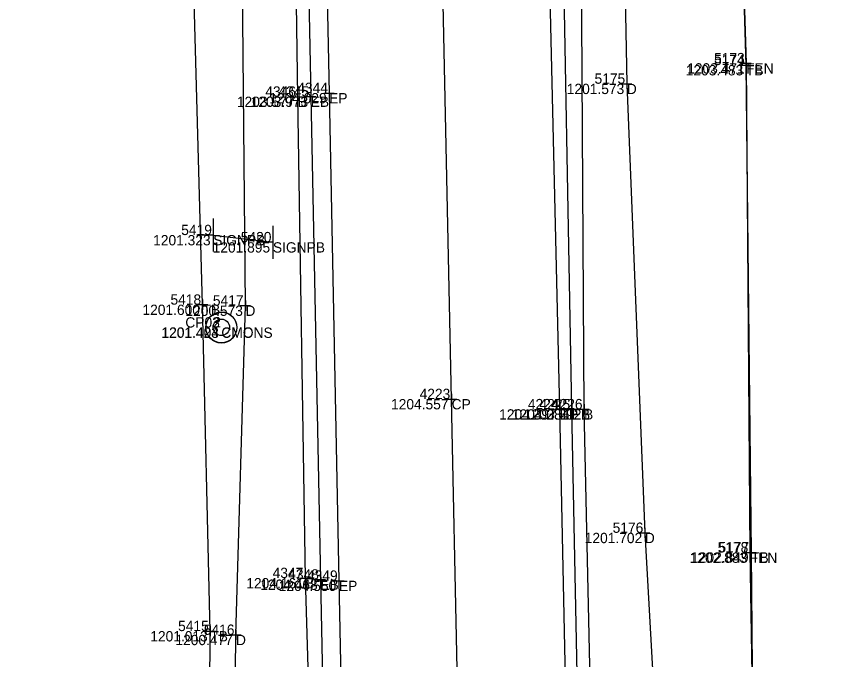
# Model space of a CAD drawing. Extents: x 2044996 to 2050343, y 455232 to 458054.
# Drawn here: x 2047583.1 to 2047663.5, y 457288.6 to 457351 of the extents above; entities that cross this region are included whole.
import ezdxf

# ---------------------------------------------------------------- set-up
doc = ezdxf.new("R2010")
doc.units = 0
for name, color, linetype in [('Default', 7, 'Continuous'), ('DR_X_Ditch', 7, 'Continuous'), ('DT_X_Contour_Minor', 7, 'Continuous'), ('DT_X_Contour_Text', 7, 'Continuous'), ('DT_X_Triangles', 7, 'Continuous'), ('DT_X_Void', 7, 'Continuous'), ('PV_X_COP', 7, 'Continuous'), ('PV_X_EOP', 7, 'Continuous'), ('PV_X_Shoulder_Aggregate', 7, 'Continuous'), ('RD_X_Fence', 7, 'Continuous'), ('SN_X_Public', 7, 'Continuous'), ('SV_P_Mon_Cells_Set', 7, 'Continuous'), ('SV_X_Break_Lines', 7, 'Continuous'), ('SV_X_Top_of_Bank', 7, 'Continuous'), ('XS_X_Ground_Line', 7, 'Continuous')]:
    doc.layers.add(name, color=color, linetype=linetype)

msp = doc.modelspace()

# ---------------------------------------------------------------- linework, layer by layer
at = {"layer": 'Default'}
msp.add_lwpolyline([(2047602.133, 457329.814), (2047607.931, 457329.117)], dxfattribs=at)
at = {"layer": 'DR_X_Ditch'}
for points in [[(2047603.882, 457240.706), (2047604.347, 457290.981), (2047605.266, 457322.964), (2047604.864, 457368.193), (2047603.186, 457417.51), (2047602.947, 457459.419), (2047602.663, 457501.838), (2047602.142, 457544.039), (2047601.082, 457584.057), (2047599.691, 457624.957), (2047599.396, 457669.272), (2047598.072, 457715.089), (2047597.975, 457762.924), (2047597.737, 457792.661), (2047596.264, 457838.201), (2047595.414, 457854.456)], [(2047635.926, 457828.454), (2047636.464, 457778.326), (2047635.665, 457731.576), (2047635.872, 457688.918), (2047636.588, 457650.583), (2047637.14, 457615.308), (2047638.364, 457574.87), (2047638.819, 457526.071), (2047639.212, 457482.918), (2047639.895, 457443.662), (2047641.237, 457398.66), (2047642.277, 457344.514), (2047644.026, 457300.889), (2047646.182, 457262.236), (2047646.962, 457237.043), (2047650.757, 457191.219), (2047650.417, 457143.89), (2047649.262, 457104.807), (2047651.899, 457052.902), (2047656.339, 457022.847)]]:
    msp.add_lwpolyline(points, dxfattribs=at)
at = {"layer": 'DT_X_Void'}
for p, q in [((2047653.853, 457347.008), (2047653.853, 457346.008)), ((2047653.326, 457346.326), (2047654.326, 457346.326)), ((2047653.353, 457346.508), (2047654.353, 457346.508)), ((2047653.826, 457346.826), (2047653.826, 457345.826)), ((2047653.826, 457346.326), (2047653.826, 457346.326)), ((2047653.853, 457346.508), (2047653.853, 457346.508)), ((2047642.277, 457345.014), (2047642.277, 457344.014)), ((2047613.384, 457344.111), (2047613.384, 457343.111)), ((2047641.777, 457344.514), (2047642.777, 457344.514)), ((2047642.277, 457344.514), (2047642.277, 457344.514)), ((2047609.815, 457343.259), (2047610.815, 457343.259)), ((2047610.315, 457343.759), (2047610.315, 457342.759)), ((2047610.315, 457343.259), (2047610.315, 457343.259)), ((2047611.099, 457343.265), (2047612.099, 457343.265)), ((2047611.599, 457343.765), (2047611.599, 457342.765)), ((2047611.599, 457343.265), (2047611.599, 457343.265)), ((2047612.884, 457343.611), (2047613.884, 457343.611)), ((2047613.384, 457343.611), (2047613.384, 457343.611)), ((2047600.608, 457323.056), (2047601.608, 457323.056)), ((2047601.108, 457323.556), (2047601.108, 457322.556)), ((2047601.108, 457323.056), (2047601.108, 457323.056)), ((2047604.766, 457322.964), (2047605.766, 457322.964)), ((2047605.266, 457323.464), (2047605.266, 457322.464)), ((2047605.266, 457322.964), (2047605.266, 457322.964)), ((2047625.275, 457314.382), (2047625.275, 457313.382)), ((2047624.775, 457313.882), (2047625.775, 457313.882)), ((2047625.275, 457313.882), (2047625.275, 457313.882)), ((2047635.764, 457313.395), (2047635.764, 457312.395)), ((2047636.928, 457313.39), (2047636.928, 457312.39)), ((2047638.128, 457313.395), (2047638.128, 457312.395)), ((2047635.264, 457312.895), (2047636.264, 457312.895)), ((2047635.764, 457312.895), (2047635.764, 457312.895)), ((2047636.428, 457312.89), (2047637.428, 457312.89)), ((2047636.928, 457312.89), (2047636.928, 457312.89)), ((2047637.628, 457312.895), (2047638.628, 457312.895)), ((2047638.128, 457312.895), (2047638.128, 457312.895)), ((2047644.026, 457301.389), (2047644.026, 457300.389)), ((2047643.526, 457300.889), (2047644.526, 457300.889)), ((2047644.026, 457300.889), (2047644.026, 457300.889)), ((2047653.708, 457298.973), (2047654.708, 457298.973)), ((2047653.835, 457298.994), (2047654.835, 457298.994)), ((2047654.208, 457299.473), (2047654.208, 457298.473)), ((2047654.208, 457298.973), (2047654.208, 457298.973)), ((2047654.335, 457299.494), (2047654.335, 457298.494)), ((2047654.335, 457298.994), (2047654.335, 457298.994)), ((2047610.564, 457296.497), (2047611.564, 457296.497)), ((2047611.064, 457296.997), (2047611.064, 457295.997)), ((2047611.064, 457296.497), (2047611.064, 457296.497)), ((2047612.033, 457296.35), (2047613.033, 457296.35)), ((2047612.533, 457296.85), (2047612.533, 457295.85)), ((2047612.533, 457296.35), (2047612.533, 457296.35)), ((2047614.337, 457296.737), (2047614.337, 457295.737)), ((2047613.837, 457296.237), (2047614.837, 457296.237)), ((2047614.337, 457296.237), (2047614.337, 457296.237)), ((2047601.855, 457291.841), (2047601.855, 457290.841)), ((2047601.355, 457291.341), (2047602.355, 457291.341)), ((2047601.855, 457291.341), (2047601.855, 457291.341)), ((2047603.847, 457290.981), (2047604.847, 457290.981)), ((2047604.347, 457291.481), (2047604.347, 457290.481)), ((2047604.347, 457290.981), (2047604.347, 457290.981))]:
    msp.add_line(p, q, dxfattribs=at)
at = {"layer": 'PV_X_COP'}
msp.add_lwpolyline([(2047630.697, 457032.772), (2047629.568, 457079.465), (2047628.826, 457121.309), (2047627.827, 457168.374), (2047627.226, 457213.893), (2047626.35, 457261.407), (2047625.275, 457313.882), (2047624.137, 457367.694), (2047623.142, 457414.957), (2047622.163, 457463.478), (2047621.208, 457510.605), (2047620.335, 457561.899), (2047619.472, 457614.832), (2047618.326, 457662.229), (2047617.507, 457713.134), (2047616.391, 457759.383), (2047615.436, 457807.272), (2047614.413, 457854.523), (2047614.295, 457881.561), (2047613.156, 457931.145), (2047612.061, 457984.051), (2047611.475, 458032.257), (2047610.912, 458052.257)], dxfattribs=at)
at = {"layer": 'PV_X_EOP'}
for p, q in [((2047612.348, 457393.643), (2047613.384, 457343.611)), ((2047635.764, 457312.895), (2047634.528, 457367.235)), ((2047613.384, 457343.611), (2047614.337, 457296.237)), ((2047636.865, 457261.4), (2047635.764, 457312.895)), ((2047614.337, 457296.237), (2047615.243, 457249.185))]:
    msp.add_line(p, q, dxfattribs=at)
at = {"layer": 'PV_X_Shoulder_Aggregate'}
for p, q in [((2047610.612, 457393.759), (2047611.599, 457343.265)), ((2047611.599, 457343.265), (2047612.533, 457296.35)), ((2047612.533, 457296.35), (2047613.535, 457249.46))]:
    msp.add_line(p, q, dxfattribs=at)
msp.add_lwpolyline([(2047765.405, 456957.602), (2047718.77, 456974.886), (2047683.466, 456987.554), (2047664.007, 456996.427), (2047655.405, 457004.196), (2047650.143, 457012.189), (2047644.762, 457024.201), (2047643.272, 457033.326), (2047642.362, 457078.681), (2047641.183, 457122.013), (2047640.211, 457169.151), (2047639.13, 457212.335), (2047637.968, 457261.485), (2047636.928, 457312.89), (2047635.932, 457367.469)], dxfattribs=at)
at = {"layer": 'RD_X_Fence'}
msp.add_lwpolyline([(2047648.142, 457619.756), (2047649.388, 457574.652), (2047649.984, 457529.132), (2047650.661, 457480.385), (2047651.7, 457447.163), (2047652.232, 457398.034), (2047653.853, 457346.508), (2047654.208, 457298.973), (2047654.823, 457261.491), (2047656.664, 457189.933), (2047656.98, 457146.63), (2047657.529, 457104.262), (2047658.626, 457057.971)], dxfattribs=at)
at = {"layer": 'SN_X_Public'}
for p, q in [((2047602.133, 457331.414), (2047602.133, 457328.214)), ((2047607.931, 457330.717), (2047607.931, 457327.517)), ((2047602.133, 457329.814), (2047600.533, 457329.814)), ((2047607.931, 457329.117), (2047606.331, 457329.117))]:
    msp.add_line(p, q, dxfattribs=at)
at = {"layer": 'SV_P_Mon_Cells_Set'}
msp.add_circle((2047602.929, 457320.83), 1.5, dxfattribs=at)
at = {"layer": 'SV_X_Break_Lines'}
for points in [[(2047609.606, 457393.106), (2047610.315, 457343.259), (2047611.064, 457296.497), (2047612.477, 457248.738), (2047612.892, 457199.618), (2047614.532, 457148.61), (2047615.457, 457101.16), (2047615.945, 457053.962), (2047615.505, 457044.294), (2047611.53, 457035.425), (2047600.94, 457028.504), (2047592.495, 457026.097), (2047589.231, 457026.308), (2047543.282, 457040.875), (2047500.592, 457056.092), (2047456.763, 457072.198), (2047414.816, 457088.31), (2047369.13, 457105.973), (2047320.737, 457125.374), (2047273.194, 457143.598), (2047227.373, 457161.688), (2047183.553, 457178.86)], [(2047766.629, 456959.742), (2047718.993, 456976.328), (2047684.007, 456989.238), (2047664.81, 456998.063), (2047657.38, 457005.807), (2047652.256, 457013.723), (2047648.313, 457024.571), (2047646.233, 457034.087), (2047644.074, 457078.243), (2047642.739, 457121.935), (2047641.844, 457169.123), (2047640.705, 457212.333), (2047639.255, 457261.637), (2047638.128, 457312.895), (2047637.801, 457367.098)]]:
    msp.add_lwpolyline(points, dxfattribs=at)
at = {"layer": 'SV_X_Top_of_Bank'}
for points in [[(2047602.072, 457232.89), (2047595.372, 457236.806), (2047596.559, 457240.434), (2047601.589, 457243.986), (2047601.855, 457291.341), (2047601.108, 457323.056), (2047599.87, 457367.876), (2047599.036, 457416.357), (2047598.258, 457460.002), (2047598.653, 457502.285), (2047597.035, 457543.457), (2047596.318, 457583.975), (2047595.268, 457626.153), (2047595.519, 457669.284), (2047593.698, 457715.003), (2047590.76, 457760.285), (2047587.575, 457790.551), (2047585.898, 457853.962)], [(2047640.567, 457829.626), (2047642.731, 457776.653), (2047644.221, 457735.314), (2047644.625, 457692.671), (2047644.932, 457653.27), (2047648.248, 457619.872), (2047649.316, 457574.484), (2047650.08, 457529.2), (2047650.597, 457480.307), (2047651.651, 457447.119), (2047652.286, 457398.02), (2047653.826, 457346.326), (2047654.335, 457298.994), (2047654.682, 457261.409), (2047656.787, 457189.888), (2047656.978, 457146.618), (2047657.585, 457104.219), (2047658.543, 457057.885), (2047659.728, 457026.437)]]:
    msp.add_lwpolyline(points, dxfattribs=at)
at = {"layer": 'XS_X_Ground_Line'}
for radius in [1.5, 0.8]:
    msp.add_circle((2047602.929, 457320.852), radius, dxfattribs=at)

# ---------------------------------------------------------------- texts
at = {"layer": 'DT_X_Contour_Minor'}
for s, p in [('1203.483', (2047648, 457345.326)), ('1203.471', (2047648.136, 457345.508)), ('1201.573', (2047636.451, 457343.514)), ('1203.577', (2047604.436, 457342.259)), ('1203.973', (2047605.773, 457342.265)), ('1204.029', (2047607.566, 457342.611)), ('1201.323', (2047596.307, 457328.814)), ('1201.895', (2047602.083, 457328.117)), ('1201.600', (2047595.271, 457322.056)), ('1200.573', (2047599.439, 457321.964)), ('1201.423', (2047597.103, 457319.83)), ('1201.404', (2047597.122, 457319.852)), ('1204.557', (2047619.395, 457312.882)), ('1204.397', (2047629.884, 457311.895)), ('1204.284', (2047631.12, 457311.89)), ('1203.892', (2047632.295, 457311.895)), ('1201.702', (2047638.193, 457299.889)), ('1202.883', (2047648.382, 457297.973)), ('1202.849', (2047648.517, 457297.994)), ('1204.161', (2047605.347, 457295.497)), ('1204.468', (2047606.697, 457295.35)), ('1204.550', (2047608.499, 457295.237)), ('1201.013', (2047596.029, 457290.341)), ('1200.477', (2047598.467, 457289.981))]:
    msp.add_text(s, height=1, dxfattribs=at).set_placement(p)
at = {"layer": 'DT_X_Contour_Text'}
for s, p in [('TB', (2047653.826, 457345.326)), ('FEN', (2047653.853, 457345.508)), ('D', (2047642.277, 457343.514)), ('B', (2047610.315, 457342.259)), ('EB', (2047611.599, 457342.265)), ('EP', (2047613.384, 457342.611)), ('SIGNPB', (2047602.133, 457328.814)), ('SIGNPB', (2047607.931, 457328.117)), ('TB', (2047601.108, 457322.056)), ('D', (2047605.266, 457321.964)), ('CMON', (2047602.929, 457319.852)), ('CMONS', (2047602.929, 457319.83)), ('CP', (2047625.275, 457312.882)), ('EP', (2047635.764, 457311.895)), ('EB', (2047636.928, 457311.89)), ('B', (2047638.128, 457311.895)), ('D', (2047644.026, 457299.889)), ('FEN', (2047654.208, 457297.973)), ('TB', (2047654.335, 457297.994)), ('B', (2047611.064, 457295.497)), ('EB', (2047612.533, 457295.35)), ('EP', (2047614.337, 457295.237)), ('TB', (2047601.855, 457290.341)), ('D', (2047604.347, 457289.981))]:
    msp.add_text(s, height=1, dxfattribs=at).set_placement(p)
at = {"layer": 'DT_X_Triangles'}
for s, p in [('5174', (2047650.736, 457346.326)), ('5173', (2047650.745, 457346.508)), ('5175', (2047639.147, 457344.514)), ('4344', (2047610.294, 457343.611)), ('4346', (2047607.193, 457343.259)), ('4345', (2047608.47, 457343.265)), ('5419', (2047599.033, 457329.814)), ('5420', (2047604.811, 457329.117)), ('5418', (2047597.99, 457323.056)), ('5417', (2047602.104, 457322.964)), ('CP03', (2047599.433, 457320.83)), ('2', (2047602.144, 457320.852)), ('4223', (2047622.167, 457313.882)), ('4224', (2047632.674, 457312.895)), ('4225', (2047633.799, 457312.89)), ('4226', (2047635.006, 457312.895)), ('5176', (2047640.903, 457300.889)), ('5178', (2047651.09, 457298.973)), ('5177', (2047651.173, 457298.994)), ('4347', (2047607.903, 457296.497)), ('4348', (2047609.415, 457296.35)), ('4349', (2047611.237, 457296.237)), ('5415', (2047598.726, 457291.341)), ('5416', (2047601.224, 457290.981))]:
    msp.add_text(s, height=1, dxfattribs=at).set_placement(p)

doc.saveas('drawing.dxf')
